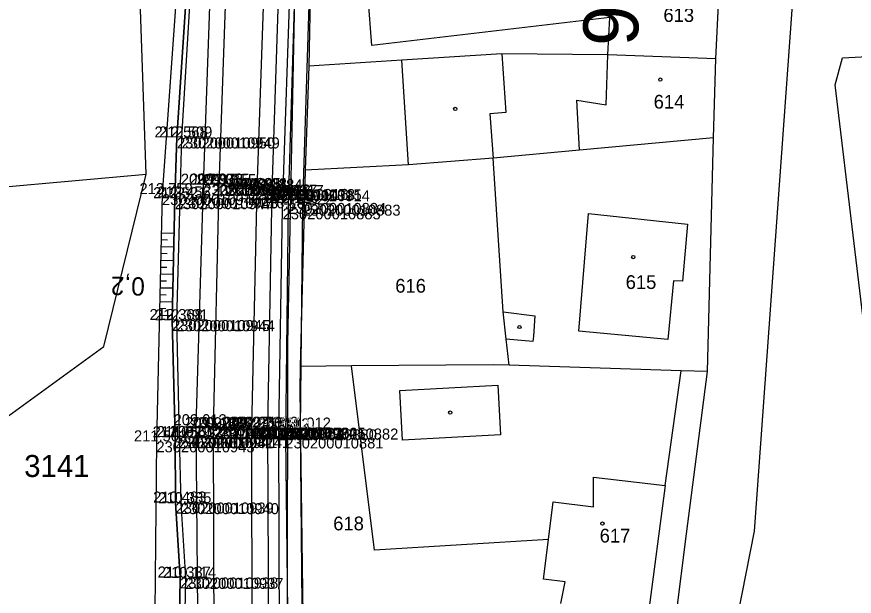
# Model space of a CAD drawing. Extents: x -563148 to -561712, y -1182311 to -1179502.
# Drawn here: x -562591.4 to -562500, y -1180838.9 to -1180775.6 of the extents above; entities that cross this region are included whole.
import ezdxf

# ---------------------------------------------------------------- set-up
doc = ezdxf.new("R2010")
doc.units = 0
for name, color, linetype in [('Vrstva 1', 7, 'Continuous'), ('Vrstva 13', 7, 'Continuous'), ('Vrstva 17', 7, 'Continuous'), ('Vrstva 4', 7, 'Continuous'), ('Vrstva 48', 7, 'Continuous'), ('Vrstva 49', 7, 'Continuous'), ('Vrstva 53', 7, 'Continuous'), ('Vrstva 55', 7, 'Continuous'), ('Vrstva 56', 7, 'Continuous'), ('Vrstva 57', 7, 'Continuous'), ('Vrstva 60', 7, 'Continuous'), ('Vrstva 61', 7, 'Continuous'), ('Vrstva 63', 7, 'Continuous'), ('Vrstva 7', 7, 'Continuous')]:
    doc.layers.add(name, color=color, linetype=linetype)

msp = doc.modelspace()

# ---------------------------------------------------------------- linework, layer by layer
at = {"layer": 'Vrstva 1'}
for points in [[(-562568.447, -1180769.256), (-562569.304, -1180793.968), (-562569.923, -1180820.538), (-562569.851, -1180844.577), (-562569.048, -1180868.505), (-562567.339, -1180894.985), (-562565.256, -1180918.218), (-562562.828, -1180942.165), (-562560.347, -1180966.087), (-562558.006, -1180988.683), (-562555.657, -1181011.477), (-562554.518, -1181022.359), (-562552.403, -1181042.927), (-562550.106, -1181065.457), (-562547.968, -1181086.047), (-562545.847, -1181106.654), (-562542.313, -1181141.048), (-562539.775, -1181165.619)], [(-562564.303, -1180769.263), (-562565.158, -1180794.441), (-562565.748, -1180820.49), (-562565.701, -1180844.542), (-562564.942, -1180867.892), (-562563.243, -1180894.349), (-562561.18, -1180917.623), (-562558.766, -1180941.515), (-562556.288, -1180965.419), (-562553.951, -1180988.015), (-562551.606, -1181010.711), (-562550.463, -1181021.746), (-562548.34, -1181042.363), (-562545.995, -1181064.902), (-562543.875, -1181085.505), (-562541.786, -1181105.972), (-562538.225, -1181140.466), (-562535.703, -1181164.996)]]:
    msp.add_lwpolyline(points, dxfattribs=at)
at = {"layer": 'Vrstva 13'}
for points in [[(-562557.976, -1181010.58), (-562558, -1181010.307), (-562558.079, -1181009.424), (-562559.927, -1180988.799), (-562562.266, -1180966.351), (-562564.717, -1180942.596), (-562567.303, -1180918.218), (-562569.432, -1180894.97), (-562570.95, -1180868.529), (-562571.576, -1180844.614), (-562571.801, -1180820.205), (-562571.006, -1180793.955), (-562570.112, -1180769.35), (-562569.341, -1180744.38), (-562569.271, -1180721.9), (-562569.501, -1180697.948), (-562571.023, -1180670.137), (-562572.171, -1180659.346), (-562572.635, -1180659.406), (-562573.467, -1180659.616), (-562573.33, -1180660.858)], [(-562560.728, -1180762.443), (-562561.766, -1180795.946), (-562562.056, -1180821.54), (-562561.768, -1180843.69), (-562561.192, -1180867.061), (-562561.397, -1180873.968), (-562559.12, -1180904.019)], [(-562561.149, -1181009.131), (-562561.24, -1181008.764), (-562559.947, -1181008.525), (-562560.154, -1181006.289), (-562562.147, -1180984.227), (-562564.005, -1180966.506), (-562565.277, -1180955.253), (-562566.403, -1180942.673), (-562569.1, -1180918.713), (-562570.551, -1180906.501), (-562571.678, -1180895.015), (-562572.932, -1180869.607), (-562573.483, -1180850.031), (-562573.549, -1180847.711), (-562573.649, -1180844.142), (-562573.538, -1180836.828), (-562574.031, -1180828.645), (-562574.084, -1180821.529), (-562574.422, -1180808.724), (-562574.116, -1180795.427), (-562573.88, -1180788.802), (-562572.624, -1180769.58)], [(-562572.217, -1180769.564), (-562573.373, -1180788.797), (-562573.562, -1180795.348), (-562573.924, -1180808.763), (-562573.634, -1180821.501), (-562573.47, -1180828.715), (-562572.964, -1180836.872), (-562573.105, -1180844.114), (-562572.333, -1180869.578), (-562571.079, -1180894.971), (-562569.955, -1180906.437), (-562568.504, -1180918.644), (-562565.806, -1180942.613), (-562564.68, -1180955.193), (-562563.435, -1180966.477), (-562561.225, -1180988.666), (-562559.67, -1181006.209), (-562559.413, -1181008.813), (-562561.149, -1181009.131)], [(-562559.663, -1180903.711), (-562560.701, -1180891.906), (-562561.896, -1180873.961), (-562561.862, -1180867.101), (-562562.709, -1180843.979), (-562562.772, -1180820.658), (-562562.354, -1180796.537), (-562561.447, -1180770.019)]]:
    msp.add_lwpolyline(points, dxfattribs=at)
at = {"layer": 'Vrstva 17'}
msp.add_lwpolyline([(-562559.404, -1180772.036), (-562560.194, -1180796.136), (-562560.44, -1180820.571), (-562560.214, -1180843.77), (-562559.552, -1180865.006)], dxfattribs=at)
at = {"layer": 'Vrstva 4'}
for points in [[(-562548.401, -1181107.417), (-562550.317, -1181086.48), (-562552.348, -1181066.066), (-562554.262, -1181043.149), (-562556.331, -1181022.59), (-562557.976, -1181010.58), (-562558, -1181010.307), (-562558.079, -1181009.424), (-562559.927, -1180988.799), (-562562.266, -1180966.351), (-562564.717, -1180942.596), (-562567.303, -1180918.218), (-562569.432, -1180894.97), (-562570.95, -1180868.529), (-562571.576, -1180844.614), (-562571.801, -1180820.205), (-562571.006, -1180793.955), (-562570.112, -1180769.35), (-562569.341, -1180744.38), (-562569.271, -1180721.9), (-562569.501, -1180697.948), (-562571.023, -1180670.137), (-562572.171, -1180659.346)], [(-562561.997, -1180660.623), (-562561.57, -1180669.053), (-562560.795, -1180699.571), (-562561.474, -1180721.983), (-562562.677, -1180769.239), (-562563.536, -1180794.555), (-562563.999, -1180820.485), (-562563.902, -1180844.088), (-562563.277, -1180867.211), (-562561.411, -1180894.209), (-562559.327, -1180917.369), (-562556.979, -1180941.413), (-562554.469, -1180965.098), (-562552.194, -1180988.078), (-562550.096, -1181008.72), (-562550.049, -1181009.182), (-562549.687, -1181012.277), (-562549.184, -1181015.02), (-562548.066, -1181022.403), (-562546.039, -1181042.458), (-562543.415, -1181064.622), (-562541.447, -1181085.622), (-562540.154, -1181099.369), (-562539.809, -1181101.815)]]:
    msp.add_lwpolyline(points, dxfattribs=at)
at = {"layer": 'Vrstva 48'}
for p, q in [((-562575.611, -1180799.196), (-562574.203, -1180799.228)), ((-562575.628, -1180799.946), (-562574.924, -1180799.962)), ((-562575.662, -1180801.446), (-562574.959, -1180801.461)), ((-562575.645, -1180800.696), (-562574.238, -1180800.728)), ((-562575.679, -1180802.195), (-562574.272, -1180802.227)), ((-562575.696, -1180802.945), (-562574.993, -1180802.961)), ((-562575.713, -1180803.695), (-562574.307, -1180803.727)), ((-562575.747, -1180805.195), (-562574.342, -1180805.226)), ((-562575.73, -1180804.445), (-562575.027, -1180804.461)), ((-562575.764, -1180805.944), (-562575.061, -1180805.96)), ((-562575.781, -1180806.694), (-562574.376, -1180806.726)), ((-562575.798, -1180807.444), (-562575.095, -1180807.46)), ((-562575.815, -1180808.194), (-562574.411, -1180808.226))]:
    msp.add_line(p, q, dxfattribs=at)
at = {"layer": 'Vrstva 49'}
for points in [[(-562607.064, -1180549.862), (-562600.314, -1180558.283), (-562595.543, -1180566.426), (-562592.496, -1180573.315), (-562587.393, -1180592.43), (-562581.787, -1180618.444), (-562580.686, -1180630.779), (-562580.558, -1180637.368), (-562579.835, -1180644.397), (-562578.413, -1180651.095), (-562577.117, -1180660.503), (-562575.242, -1180669.932), (-562574.805, -1180684.994), (-562573.827, -1180697.073), (-562573.884, -1180726.371), (-562573.545, -1180743.64), (-562573.704, -1180769.923), (-562575.516, -1180794.984), (-562576.126, -1180821.969), (-562576.339, -1180844.251), (-562576.036, -1180847.781)], [(-562572.624, -1180769.58), (-562573.88, -1180788.802), (-562574.116, -1180795.427), (-562574.422, -1180808.724), (-562574.084, -1180821.529), (-562574.031, -1180828.645), (-562573.538, -1180836.828), (-562573.649, -1180844.142), (-562573.549, -1180847.711), (-562573.483, -1180850.031), (-562572.932, -1180869.607), (-562571.678, -1180895.015), (-562570.551, -1180906.501), (-562569.1, -1180918.713), (-562566.403, -1180942.673), (-562565.277, -1180955.253), (-562564.005, -1180966.506), (-562562.147, -1180984.227), (-562560.154, -1181006.289), (-562559.947, -1181008.525), (-562561.24, -1181008.764)]]:
    msp.add_lwpolyline(points, dxfattribs=at)
at = {"layer": 'Vrstva 53'}
for p, q in [((-562561.04, -1180771.93), (-562561.81, -1180811.3)), ((-562577.23, -1180792.79), (-562577.9, -1180773.76)), ((-562581.87, -1180811.63), (-562577.23, -1180792.79)), ((-562595.23, -1180821.34), (-562581.87, -1180811.63)), ((-562561.81, -1180811.3), (-562561.86, -1180843.17))]:
    msp.add_line(p, q, dxfattribs=at)
at = {"layer": 'Vrstva 55'}
for p, q in [((-562515.09, -1180780.21), (-562514.53, -1180768.7)), ((-562559.32, -1180771.84), (-562559.49, -1180781.01)), ((-562549.35, -1180780.38), (-562559.49, -1180781.01)), ((-562538.44, -1180779.67), (-562549.35, -1180780.38)), ((-562526.86, -1180779.79), (-562538.44, -1180779.67)), ((-562515.09, -1180780.21), (-562526.86, -1180779.79)), ((-562515.34, -1180788.83), (-562515.09, -1180780.21)), ((-562559.49, -1180781.01), (-562559.9, -1180792.36)), ((-562497.9, -1180817.7), (-562502.07, -1180783.04)), ((-562515.34, -1180788.83), (-562529.96, -1180790.18)), ((-562515.98, -1180814.33), (-562515.34, -1180788.83)), ((-562529.96, -1180790.18), (-562539.37, -1180791.05)), ((-562539.37, -1180791.05), (-562548.62, -1180791.77)), ((-562538.27, -1180807.83), (-562539.37, -1180791.05)), ((-562559.9, -1180792.36), (-562560.45, -1180813.79)), ((-562548.62, -1180791.77), (-562559.9, -1180792.36)), ((-562612.76, -1180796.03), (-562577.23, -1180792.79)), ((-562537.95, -1180810.82), (-562538.27, -1180807.83)), ((-562537.64, -1180813.66), (-562537.95, -1180810.82)), ((-562560.45, -1180813.79), (-562560.47, -1180816.34)), ((-562554.85, -1180813.74), (-562560.45, -1180813.79)), ((-562539.37, -1180813.6), (-562554.85, -1180813.74)), ((-562552.33, -1180833.83), (-562554.85, -1180813.74)), ((-562537.64, -1180813.66), (-562539.37, -1180813.6)), ((-562518.86, -1180814.28), (-562537.64, -1180813.66)), ((-562515.98, -1180814.33), (-562518.86, -1180814.28)), ((-562518.27, -1180832.07), (-562515.98, -1180814.33)), ((-562560.47, -1180816.34), (-562560.12, -1180843.61)), ((-562519.5, -1180841.68), (-562518.27, -1180832.07)), ((-562533.35, -1180832.68), (-562552.33, -1180833.83)), ((-562533.89, -1180837.01), (-562533.35, -1180832.68)), ((-562531.53, -1180837.31), (-562533.89, -1180837.01)), ((-562531.98, -1180839.66), (-562531.53, -1180837.31))]:
    msp.add_line(p, q, dxfattribs=at)
at = {"layer": 'Vrstva 56'}
for p, q in [((-562552.63, -1180778.78), (-562553.13, -1180771.72)), ((-562510.87, -1180831.78), (-562506.72, -1180774.36)), ((-562526.63, -1180775.69), (-562552.63, -1180778.78)), ((-562526.86, -1180779.79), (-562526.63, -1180775.69)), ((-562548.62, -1180791.77), (-562549.35, -1180780.38)), ((-562538.44, -1180779.67), (-562538.01, -1180786.09)), ((-562527.06, -1180785.25), (-562526.86, -1180779.79)), ((-562502.07, -1180783.04), (-562501.25, -1180780.1)), ((-562501.25, -1180780.1), (-562497.75, -1180779.94)), ((-562529.96, -1180790.18), (-562530.23, -1180784.73)), ((-562530.23, -1180784.73), (-562527.06, -1180785.25)), ((-562538.01, -1180786.09), (-562539.74, -1180786.22)), ((-562539.74, -1180786.22), (-562539.37, -1180791.05)), ((-562530.01, -1180809.93), (-562528.97, -1180797.1)), ((-562528.97, -1180797.1), (-562518.18, -1180798.26)), ((-562518.18, -1180798.26), (-562518.7, -1180804.49)), ((-562519.71, -1180804.44), (-562520.32, -1180810.86)), ((-562518.7, -1180804.49), (-562519.71, -1180804.44)), ((-562538.27, -1180807.83), (-562534.83, -1180808.26)), ((-562534.83, -1180808.26), (-562534.99, -1180810.49)), ((-562534.99, -1180810.49), (-562535.03, -1180811.07)), ((-562520.32, -1180810.86), (-562530.01, -1180809.93)), ((-562535.03, -1180811.07), (-562537.95, -1180810.82)), ((-562520.6, -1180826.79), (-562518.86, -1180814.28)), ((-562549.58, -1180816.4), (-562538.86, -1180815.84)), ((-562538.86, -1180815.84), (-562538.56, -1180821.25)), ((-562549.28, -1180821.84), (-562549.58, -1180816.4)), ((-562538.56, -1180821.25), (-562549.28, -1180821.84)), ((-562528.41, -1180829.11), (-562528.43, -1180825.88)), ((-562528.43, -1180825.88), (-562520.6, -1180826.79)), ((-562520.6, -1180826.79), (-562522.46, -1180840.9)), ((-562533.35, -1180832.68), (-562532.83, -1180828.58)), ((-562532.83, -1180828.58), (-562528.41, -1180829.11)), ((-562514.35, -1180849.4), (-562510.87, -1180831.78))]:
    msp.add_line(p, q, dxfattribs=at)
at = {"layer": 'Vrstva 57'}
for centre in [(-562521.14, -1180782.48), (-562543.52, -1180785.68), (-562524.09, -1180801.86), (-562536.5, -1180809.49), (-562544.059, -1180818.83), (-562527.449, -1180830.94)]:
    msp.add_circle(centre, 0.175, dxfattribs=at)
at = {"layer": 'Vrstva 60'}
for p, q in [((-562573.88, -1180788.802), (-562573.88, -1180788.802)), ((-562573.373, -1180788.797), (-562573.373, -1180788.797)), ((-562571.006, -1180793.955), (-562571.006, -1180793.955)), ((-562570.022, -1180793.935), (-562570.022, -1180793.935)), ((-562569.304, -1180793.968), (-562569.304, -1180793.968)), ((-562568.587, -1180794), (-562568.587, -1180794)), ((-562575.516, -1180794.984), (-562575.516, -1180794.984)), ((-562565.882, -1180794.419), (-562565.882, -1180794.419)), ((-562565.158, -1180794.441), (-562565.158, -1180794.441)), ((-562564.434, -1180794.462), (-562564.434, -1180794.462)), ((-562563.536, -1180794.555), (-562563.536, -1180794.555)), ((-562574.116, -1180795.427), (-562574.116, -1180795.427)), ((-562573.562, -1180795.348), (-562573.562, -1180795.348)), ((-562561.766, -1180795.946), (-562561.766, -1180795.946)), ((-562562.354, -1180796.537), (-562562.354, -1180796.537)), ((-562560.194, -1180796.136), (-562560.194, -1180796.136)), ((-562574.422, -1180808.724), (-562574.422, -1180808.724)), ((-562573.924, -1180808.763), (-562573.924, -1180808.763)), ((-562571.801, -1180820.205), (-562571.801, -1180820.205)), ((-562570.649, -1180820.535), (-562570.649, -1180820.535)), ((-562569.923, -1180820.538), (-562569.923, -1180820.538)), ((-562569.197, -1180820.541), (-562569.197, -1180820.541)), ((-562566.47, -1180820.485), (-562566.47, -1180820.485)), ((-562565.748, -1180820.49), (-562565.748, -1180820.49)), ((-562565.027, -1180820.495), (-562565.027, -1180820.495)), ((-562563.999, -1180820.485), (-562563.999, -1180820.485)), ((-562562.772, -1180820.658), (-562562.772, -1180820.658)), ((-562560.44, -1180820.571), (-562560.44, -1180820.571)), ((-562574.084, -1180821.529), (-562574.084, -1180821.529)), ((-562573.634, -1180821.501), (-562573.634, -1180821.501)), ((-562572.235, -1180821.484), (-562572.235, -1180821.484)), ((-562562.056, -1180821.54), (-562562.056, -1180821.54)), ((-562576.126, -1180821.969), (-562576.126, -1180821.969)), ((-562574.031, -1180828.645), (-562574.031, -1180828.645)), ((-562573.47, -1180828.715), (-562573.47, -1180828.715)), ((-562573.538, -1180836.828), (-562573.538, -1180836.828)), ((-562572.964, -1180836.872), (-562572.964, -1180836.872))]:
    msp.add_line(p, q, dxfattribs=at)
at = {"layer": 'Vrstva 63'}
msp.add_line((-562572.285, -1180821.484), (-562572.185, -1180821.484), dxfattribs=at)
msp.add_circle((-562572.235, -1180821.484), 0.756, dxfattribs=at)

# ---------------------------------------------------------------- texts
at = {"layer": 'Vrstva 48'}
msp.add_text('0,2', height=2, rotation=178.70504, dxfattribs=at).set_placement((-562577.367, -1180804.073))
at = {"layer": 'Vrstva 57'}
for s, p in [('613', (-562520.798, -1180776.19)), ('614', (-562521.86, -1180785.65)), ('616', (-562550.062, -1180805.74)), ('615', (-562524.917, -1180805.34)), ('618', (-562556.832, -1180831.68)), ('617', (-562527.753, -1180833.008))]:
    msp.add_text(s, height=1.5, dxfattribs=at).set_placement(p)
at = {"layer": 'Vrstva 60'}
for s, p in [('230200010950', (-562573.88, -1180790.002)), ('230200010949', (-562573.373, -1180789.997)), ('230200010919', (-562571.006, -1180795.155)), ('230200010918', (-562570.022, -1180795.135)), ('230200011477', (-562569.304, -1180795.168)), ('230200010917', (-562568.587, -1180795.2)), ('230200010946', (-562575.516, -1180796.184)), ('230200010916', (-562565.882, -1180795.619)), ('230200011478', (-562565.158, -1180795.641)), ('230200010915', (-562564.434, -1180795.662)), ('230200010914', (-562563.536, -1180795.755)), ('230200010947', (-562574.116, -1180796.627)), ('230200010948', (-562573.562, -1180796.548)), ('230200010884', (-562561.766, -1180797.146)), ('230200010885', (-562562.354, -1180797.737)), ('230200010883', (-562560.194, -1180797.336)), ('230200010945', (-562574.422, -1180809.924)), ('230200010944', (-562573.924, -1180809.963)), ('230200010920', (-562571.801, -1180821.405)), ('230200010921', (-562570.649, -1180821.735)), ('230200011475', (-562569.923, -1180821.738)), ('230200010922', (-562569.197, -1180821.741)), ('230200010923', (-562566.47, -1180821.685)), ('230200011476', (-562565.748, -1180821.69)), ('230200010924', (-562565.027, -1180821.695)), ('230200010925', (-562563.999, -1180821.685)), ('230200010880', (-562562.772, -1180821.858)), ('230200010882', (-562560.44, -1180821.771)), ('230200010942', (-562574.084, -1180822.729)), ('230200010941', (-562573.634, -1180822.701)), ('230200003141', (-562572.235, -1180822.684)), ('230200010881', (-562562.056, -1180822.74)), ('230200010943', (-562576.126, -1180823.169)), ('230200010939', (-562574.031, -1180829.845)), ('230200010940', (-562573.47, -1180829.915)), ('230200010938', (-562573.538, -1180838.028)), ('230200010937', (-562572.964, -1180838.072))]:
    msp.add_text(s, height=1.2, dxfattribs=at).set_placement(p)
at = {"layer": 'Vrstva 61'}
for s, p in [('212.568', (-562576.334, -1180788.802)), ('212.509', (-562575.827, -1180788.797)), ('209.200', (-562573.457, -1180793.955)), ('209.378', (-562572.476, -1180793.935)), ('209.355', (-562571.76, -1180793.968)), ('209.355', (-562571.043, -1180794)), ('209.395', (-562568.338, -1180794.419)), ('209.381', (-562567.515, -1180794.441)), ('209.381', (-562566.791, -1180794.462)), ('209.184', (-562565.987, -1180794.555)), ('212.759', (-562577.97, -1180794.984)), ('212.521', (-562576.473, -1180795.427)), ('212.456', (-562576.014, -1180795.348)), ('210.120', (-562564.217, -1180795.946)), ('210.222', (-562562.642, -1180796.136)), ('210.187', (-562564.806, -1180796.537)), ('212.368', (-562576.876, -1180808.724)), ('212.391', (-562576.281, -1180808.763)), ('209.013', (-562574.253, -1180820.205)), ('209.221', (-562573.006, -1180820.535)), ('209.188', (-562572.377, -1180820.538)), ('209.188', (-562571.651, -1180820.541)), ('209.271', (-562568.827, -1180820.485)), ('209.236', (-562568.2, -1180820.49)), ('209.236', (-562567.479, -1180820.495)), ('209.009', (-562566.453, -1180820.485)), ('210.802', (-562565.22, -1180820.658)), ('211.012', (-562562.888, -1180820.571)), ('211.502', (-562578.574, -1180821.969)), ('211.056', (-562576.536, -1180821.529)), ('211.029', (-562576.088, -1180821.501)), ('209.012', (-562574.683, -1180821.484)), ('210.721', (-562564.413, -1180821.54)), ('210.483', (-562576.483, -1180828.645)), ('210.385', (-562575.926, -1180828.715)), ('210.337', (-562575.99, -1180836.828)), ('210.114', (-562575.415, -1180836.872))]:
    msp.add_text(s, height=1.2, dxfattribs=at).set_placement(p)
at = {"layer": 'Vrstva 63'}
msp.add_text('3141', height=2.4, dxfattribs=at).set_placement((-562590.559, -1180825.855))
at = {"layer": 'Vrstva 7'}
msp.add_text('58,6', height=6, rotation=268.25557, dxfattribs=at).set_placement((-562529.127, -1180763.109))

doc.saveas('drawing.dxf')
